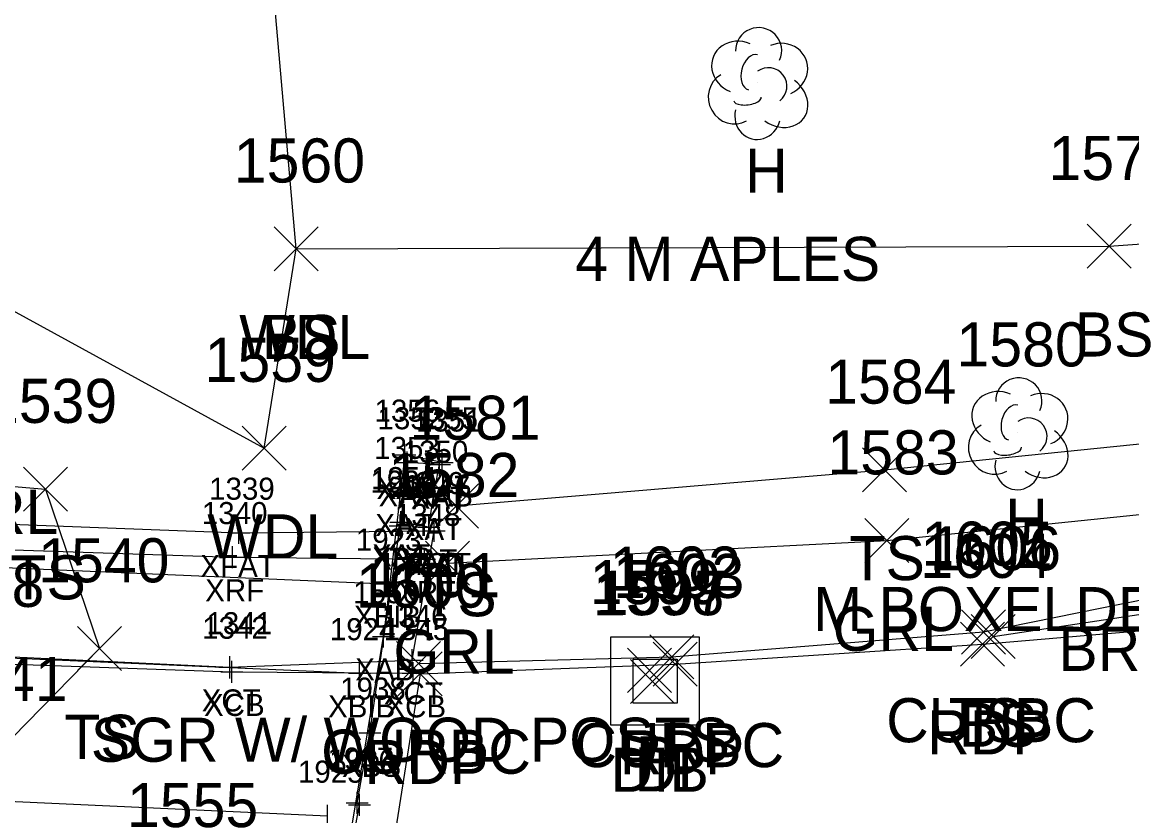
# Model space of a CAD drawing. Extents: x 1761340 to 1763889, y 696770 to 706023.
# Drawn here: x 1761711.3 to 1761761.6, y 700846.3 to 700882.3 of the extents above; entities that cross this region are included whole.
import ezdxf

# ---------------------------------------------------------------- set-up
doc = ezdxf.new("R2010")
doc.units = 0
for name, color, linetype in [('B_A', 7, 'Continuous'), ('B_I', 7, 'Continuous'), ('B_TIC', 7, 'Continuous'), ('BB', 7, 'Continuous'), ('BDC', 7, 'Continuous'), ('BF', 7, 'Continuous'), ('BR', 7, 'Continuous'), ('BSE', 7, 'Continuous'), ('BSUBM', 7, 'Continuous'), ('C_A', 7, 'Continuous'), ('D_A', 7, 'Continuous'), ('D_I', 7, 'Continuous'), ('D_TIC', 7, 'Continuous'), ('DS', 7, 'Continuous'), ('L_A', 7, 'Continuous'), ('L_C', 7, 'Continuous'), ('L_I', 7, 'Continuous'), ('L_TIC', 7, 'Continuous'), ('LAWA', 7, 'Continuous'), ('LELB', 7, 'Continuous'), ('LTD', 7, 'Continuous'), ('P_A', 7, 'Continuous'), ('P_I', 7, 'Continuous'), ('P_TIC', 7, 'Continuous'), ('PET', 7, 'Continuous'), ('R_A', 7, 'Continuous'), ('R_C', 7, 'Continuous'), ('R_I', 7, 'Continuous'), ('R_TIC', 7, 'Continuous'), ('RC', 7, 'Continuous'), ('RGR', 7, 'Continuous'), ('S_C', 7, 'Continuous')]:
    doc.layers.add(name, color=color, linetype=linetype)

msp = doc.modelspace()

# ---------------------------------------------------------------- linework, layer by layer
at = {"layer": 'B_TIC'}
for p, q in [((1761728.645, 700862.669), (1761728.721, 700862.669)), ((1761728.75, 700862.324), (1761728.825, 700862.324)), ((1761730.213, 700862.22), (1761730.289, 700862.22)), ((1761730.336, 700862.319), (1761730.412, 700862.319)), ((1761728.602, 700860.981), (1761728.678, 700860.981)), ((1761729.939, 700860.804), (1761730.014, 700860.804)), ((1761728.433, 700859.454), (1761728.508, 700859.454)), ((1761728.46, 700859.609), (1761728.536, 700859.609)), ((1761728.46, 700859.609), (1761728.536, 700859.609)), ((1761729.726, 700859.385), (1761729.802, 700859.385)), ((1761729.726, 700859.385), (1761729.802, 700859.385)), ((1761729.971, 700859.215), (1761730.046, 700859.215)), ((1761729.971, 700859.215), (1761730.046, 700859.215)), ((1761721.123, 700859.13), (1761721.199, 700859.13)), ((1761720.834, 700858.025), (1761720.91, 700858.025)), ((1761729.543, 700857.943), (1761729.618, 700857.943)), ((1761727.771, 700856.824), (1761727.846, 700856.824)), ((1761727.678, 700854.438), (1761727.753, 700854.438)), ((1761727.678, 700854.438), (1761727.753, 700854.438)), ((1761728.976, 700853.355), (1761729.052, 700853.355)), ((1761720.715, 700853.034), (1761720.79, 700853.034)), ((1761720.805, 700852.829), (1761720.881, 700852.829)), ((1761726.594, 700852.762), (1761726.67, 700852.762)), ((1761729.03, 700852.764), (1761729.105, 700852.764)), ((1761727.06, 700850.068), (1761727.135, 700850.068)), ((1761726.487, 700846.895), (1761726.563, 700846.895)), ((1761726.589, 700846.803), (1761726.665, 700846.803))]:
    msp.add_line(p, q, dxfattribs=at)
for points in [[(1761728.642, 700862.169), (1761728.642, 700863.169)], [(1761728.746, 700861.824), (1761728.746, 700862.824)], [(1761730.21, 700861.72), (1761730.21, 700862.72)], [(1761730.333, 700861.819), (1761730.333, 700862.819)], [(1761728.142, 700862.669), (1761729.142, 700862.669)], [(1761728.246, 700862.324), (1761729.246, 700862.324)], [(1761729.71, 700862.22), (1761730.71, 700862.22)], [(1761729.833, 700862.319), (1761730.833, 700862.319)], [(1761728.599, 700860.481), (1761728.599, 700861.481)], [(1761729.935, 700860.304), (1761729.935, 700861.304)], [(1761728.099, 700860.981), (1761729.099, 700860.981)], [(1761729.435, 700860.804), (1761730.435, 700860.804)], [(1761728.429, 700858.954), (1761728.429, 700859.954)], [(1761728.457, 700859.109), (1761728.457, 700860.109)], [(1761728.457, 700859.109), (1761728.457, 700860.109)], [(1761729.723, 700858.885), (1761729.723, 700859.885)], [(1761729.723, 700858.885), (1761729.723, 700859.885)], [(1761729.967, 700858.715), (1761729.967, 700859.715)], [(1761729.967, 700858.715), (1761729.967, 700859.715)], [(1761721.12, 700858.63), (1761721.12, 700859.63)], [(1761727.929, 700859.454), (1761728.929, 700859.454)], [(1761727.957, 700859.609), (1761728.957, 700859.609)], [(1761727.957, 700859.609), (1761728.957, 700859.609)], [(1761729.223, 700859.385), (1761730.223, 700859.385)], [(1761729.223, 700859.385), (1761730.223, 700859.385)], [(1761729.467, 700859.215), (1761730.467, 700859.215)], [(1761729.467, 700859.215), (1761730.467, 700859.215)], [(1761720.62, 700859.13), (1761721.62, 700859.13)], [(1761720.831, 700857.525), (1761720.831, 700858.525)], [(1761729.539, 700857.443), (1761729.539, 700858.443)], [(1761720.331, 700858.025), (1761721.331, 700858.025)], [(1761729.039, 700857.943), (1761730.039, 700857.943)], [(1761727.767, 700856.324), (1761727.767, 700857.324)], [(1761727.267, 700856.824), (1761728.267, 700856.824)], [(1761727.674, 700853.938), (1761727.674, 700854.938)], [(1761727.674, 700853.938), (1761727.674, 700854.938)], [(1761727.174, 700854.438), (1761728.174, 700854.438)], [(1761727.174, 700854.438), (1761728.174, 700854.438)], [(1761728.973, 700852.855), (1761728.973, 700853.855)], [(1761720.711, 700852.534), (1761720.711, 700853.534)], [(1761720.802, 700852.329), (1761720.802, 700853.329)], [(1761726.591, 700852.262), (1761726.591, 700853.262)], [(1761728.473, 700853.355), (1761729.473, 700853.355)], [(1761729.026, 700852.264), (1761729.026, 700853.264)], [(1761720.211, 700853.034), (1761721.211, 700853.034)], [(1761720.302, 700852.829), (1761721.302, 700852.829)], [(1761726.091, 700852.762), (1761727.091, 700852.762)], [(1761728.526, 700852.764), (1761729.526, 700852.764)], [(1761727.056, 700849.568), (1761727.056, 700850.568)], [(1761726.556, 700850.068), (1761727.556, 700850.068)], [(1761726.484, 700846.395), (1761726.484, 700847.395)], [(1761726.586, 700846.303), (1761726.586, 700847.303)], [(1761725.143, 700845.803), (1761725.143, 700846.803)], [(1761725.984, 700846.895), (1761726.984, 700846.895)], [(1761726.086, 700846.803), (1761727.086, 700846.803)]]:
    msp.add_lwpolyline(points, dxfattribs=at)
at = {"layer": 'BB'}
for points in [[(1761688.646, 700858.499), (1761727.767, 700856.824)], [(1761687.919, 700854.467), (1761726.591, 700852.762)], [(1761686.963, 700848.05), (1761725.143, 700846.303)]]:
    msp.add_lwpolyline(points, dxfattribs=at)
at = {"layer": 'BDC'}
for points in [[(1761603.372, 700879.329), (1761602.459, 700873.228), (1761625.807, 700865.915), (1761643.998, 700861.743), (1761666.42, 700857.506), (1761686.349, 700855.322), (1761703.242, 700853.873), (1761720.711, 700853.034), (1761728.973, 700853.355), (1761729.967, 700859.215)], [(1761602.35, 700873.051), (1761625.784, 700865.689), (1761644.021, 700861.397), (1761666.64, 700857.269), (1761686.143, 700854.84), (1761703.209, 700853.454), (1761720.802, 700852.829), (1761729.026, 700852.764)]]:
    msp.add_lwpolyline(points, dxfattribs=at)
at = {"layer": 'BF'}
msp.add_lwpolyline([(1761603.372, 700879.329), (1761627.262, 700871.889), (1761644.624, 700867.82), (1761667.288, 700863.505), (1761686.862, 700861.108), (1761704.425, 700859.764), (1761721.12, 700859.13), (1761729.967, 700859.215)], dxfattribs=at)
at = {"layer": 'BR'}
msp.add_lwpolyline([(1761603.404, 700877.977), (1761626.827, 700870.765), (1761644.368, 700866.459), (1761666.987, 700862.382), (1761686.603, 700859.803), (1761703.665, 700858.606), (1761720.831, 700858.025), (1761729.539, 700857.943)], dxfattribs=at)
at = {"layer": 'BSE'}
msp.add_lwpolyline([(1761723.35, 700827.699), (1761724.274, 700832.64), (1761724.336, 700832.656), (1761725.187, 700838.449), (1761725.221, 700838.487), (1761725.923, 700842.984), (1761725.977, 700843.546), (1761726.586, 700846.803), (1761726.484, 700846.895), (1761727.056, 700850.068), (1761728.429, 700859.454)], dxfattribs=at)
at = {"layer": 'BSUBM'}
for points in [[(1761730.333, 700862.319), (1761728.642, 700862.669), (1761727.674, 700854.438)], [(1761729.723, 700859.385), (1761729.935, 700860.804), (1761730.21, 700862.22), (1761728.746, 700862.324), (1761728.599, 700860.981), (1761728.457, 700859.609)], [(1761729.723, 700859.385), (1761728.457, 700859.609)], [(1761724.634, 700825.932), (1761724.461, 700823.944), (1761722.479, 700824.16), (1761722.925, 700826.757), (1761723.41, 700828.779), (1761727.674, 700854.438)]]:
    msp.add_lwpolyline(points, dxfattribs=at)
at = {"layer": 'D_TIC'}
for points in [[(1761738.729, 700851.898), (1761740.729, 700853.898)], [(1761740.729, 700851.898), (1761738.729, 700853.898)], [(1761738.865, 700851.393), (1761740.865, 700853.393)], [(1761740.865, 700851.393), (1761738.865, 700853.393)]]:
    msp.add_lwpolyline(points, dxfattribs=at)
at = {"layer": 'DS'}
for p, q in [((1761737.987, 700854.41), (1761741.987, 700854.41)), ((1761737.987, 700850.41), (1761737.987, 700854.41)), ((1761741.987, 700854.41), (1761741.987, 700850.41)), ((1761738.987, 700851.41), (1761738.987, 700853.41)), ((1761738.987, 700853.41), (1761740.987, 700853.41)), ((1761740.987, 700853.41), (1761740.987, 700851.41)), ((1761739.992, 700852.412), (1761739.992, 700852.412)), ((1761739.992, 700852.412), (1761739.992, 700852.412)), ((1761740.987, 700851.41), (1761738.987, 700851.41)), ((1761741.987, 700850.41), (1761737.987, 700850.41))]:
    msp.add_line(p, q, dxfattribs=at)
at = {"layer": 'L_TIC'}
for points in [[(1761722.716, 700871.008), (1761724.716, 700873.008)], [(1761724.716, 700871.008), (1761722.716, 700873.008)], [(1761722.716, 700871.008), (1761724.716, 700873.008)], [(1761724.716, 700871.008), (1761722.716, 700873.008)], [(1761759.57, 700871.122), (1761761.57, 700873.122)], [(1761761.57, 700871.122), (1761759.57, 700873.122)], [(1761721.268, 700861.97), (1761723.268, 700863.97)], [(1761723.268, 700861.97), (1761721.268, 700863.97)], [(1761749.391, 700860.984), (1761751.391, 700862.984)], [(1761751.391, 700860.984), (1761749.391, 700862.984)], [(1761711.355, 700860.111), (1761713.355, 700862.111)], [(1761713.355, 700860.111), (1761711.355, 700862.111)], [(1761729.978, 700859.347), (1761731.978, 700861.347)], [(1761731.978, 700859.347), (1761729.978, 700861.347)], [(1761753.879, 700853.636), (1761755.879, 700855.636)], [(1761755.879, 700853.636), (1761753.879, 700855.636)], [(1761754.317, 700853.431), (1761756.317, 700855.431)], [(1761756.317, 700853.431), (1761754.317, 700855.431)], [(1761713.798, 700852.885), (1761715.798, 700854.885)], [(1761715.798, 700852.885), (1761713.798, 700854.885)]]:
    msp.add_lwpolyline(points, dxfattribs=at)
at = {"layer": 'LAWA'}
msp.add_lwpolyline([(1761696.403, 700877.132), (1761722.268, 700862.97), (1761723.716, 700872.008), (1761721.644, 700895.629), (1761726.277, 700910.333), (1761732.763, 700919.168), (1761734.997, 700942.591)], dxfattribs=at)
at = {"layer": 'LELB'}
for points in [[(1761723.716, 700872.008), (1761760.57, 700872.122), (1761783.532, 700873.77), (1761799.17, 700869.892), (1761806.338, 700870.908), (1761834.789, 700874.305), (1761863.419, 700878.597), (1761884.027, 700880.868), (1761911.516, 700884.533), (1761932.354, 700886.896), (1761937.155, 700891.638), (1761941.248, 700901.223)], [(1761730.978, 700860.347), (1761750.391, 700861.984), (1761774.561, 700864.449), (1761784.543, 700864.299)], [(1761754.879, 700854.636), (1761779.614, 700859.653), (1761806.29, 700864.673)], [(1761755.317, 700854.431), (1761780.015, 700858.17), (1761806.29, 700864.673)], [(1761687.875, 700863.195), (1761712.355, 700861.111), (1761714.798, 700853.885), (1761709.534, 700848.506), (1761700.41, 700847.52), (1761692.689, 700848.437), (1761689.436, 700852.719)]]:
    msp.add_lwpolyline(points, dxfattribs=at)
at = {"layer": 'LTD'}
for p, q in [((1761744.635, 700879.551), (1761744.635, 700879.551)), ((1761744.635, 700879.551), (1761744.635, 700879.551)), ((1761756.429, 700863.673), (1761756.429, 700863.673)), ((1761756.429, 700863.673), (1761756.429, 700863.673))]:
    msp.add_line(p, q, dxfattribs=at)
for centre in [(1761744.681, 700880.985), (1761756.476, 700865.107)]:
    msp.add_arc(centre, 1.047, 335.5272, 180.9563, dxfattribs=at)
for centre, major_axis, ratio, start_param, end_param in [((1761743.843, 700880.217), (1.21, -0.512), 0.895232, 1.570796, 4.712389), ((1761745.676, 700880.134), (-1.141, -0.483), 0.949671, 1.570796, 4.712389), ((1761744.426, 700880.009), (-0.208, -0.792), 0.645439, 3.141593, 6.283185), ((1761745.135, 700879.384), (-0.5, 0.667), 0.989748, 3.141593, 6.283185), ((1761743.551, 700878.842), (0.584, -1.042), 0.959034, 3.141593, 6.283185), ((1761745.635, 700878.717), (-1.09, 0.792), 0.841452, 1.570796, 4.712389), ((1761744.176, 700878.8), (-0.625, -0.083), 0.423636, 0, 3.141593), ((1761744.635, 700878.051), (0.265, 1.061), 0.942809, 1.570796, 4.712389), ((1761755.638, 700864.339), (1.21, -0.512), 0.895232, 1.570796, 4.712389), ((1761757.471, 700864.256), (-1.141, -0.483), 0.949671, 1.570796, 4.712389), ((1761756.221, 700864.131), (-0.208, -0.792), 0.645439, 3.141593, 6.283185), ((1761756.929, 700863.506), (-0.5, 0.667), 0.989748, 3.141593, 6.283185), ((1761755.346, 700862.964), (0.584, -1.042), 0.959034, 3.141593, 6.283185), ((1761757.429, 700862.839), (-1.09, 0.792), 0.841452, 1.570796, 4.712389), ((1761755.971, 700862.923), (-0.625, -0.083), 0.423636, 0, 3.141593), ((1761756.43, 700862.173), (0.265, 1.061), 0.942809, 1.570796, 4.712389)]:
    msp.add_ellipse(centre, major_axis=major_axis, ratio=ratio, start_param=start_param, end_param=end_param, dxfattribs=at)
at = {"layer": 'P_TIC'}
for points in [[(1761753.829, 700853.087), (1761755.829, 700855.087)], [(1761755.829, 700853.087), (1761753.829, 700855.087)], [(1761739.899, 700852.176), (1761741.899, 700854.176)], [(1761741.899, 700852.176), (1761739.899, 700854.176)], [(1761728.332, 700851.74), (1761730.332, 700853.74)], [(1761730.332, 700851.74), (1761728.332, 700853.74)], [(1761728.332, 700851.74), (1761730.332, 700853.74)], [(1761730.332, 700851.74), (1761728.332, 700853.74)]]:
    msp.add_lwpolyline(points, dxfattribs=at)
at = {"layer": 'PET'}
for points in [[(1761729.332, 700852.74), (1761740.899, 700853.176), (1761754.829, 700854.087), (1761780.546, 700856.275), (1761810.222, 700861.143), (1761821.192, 700866.007), (1761839.219, 700868.834), (1761861.11, 700872.048), (1761884.874, 700875.705), (1761913.75, 700879.268), (1761932.441, 700880.62), (1761962.057, 700884.589), (1761979.873, 700885.617), (1762011.623, 700885.448), (1762036.796, 700884.842)], [(1761729.332, 700852.74), (1761727.434, 700840.665), (1761725.471, 700828.383), (1761741.06, 700828.317), (1761766.654, 700830.86), (1761785.895, 700834.25), (1761810.857, 700839.794), (1761840.513, 700846.054), (1761863.887, 700848.795), (1761886.859, 700850.872), (1761909.086, 700853.948), (1761931.553, 700856.455), (1761961.834, 700859.608), (1761986.639, 700861.179), (1762018.608, 700861.2), (1762035.735, 700860.872)]]:
    msp.add_lwpolyline(points, dxfattribs=at)
at = {"layer": 'R_TIC'}
for points in [[(1761749.494, 700857.778), (1761751.494, 700859.778)], [(1761751.494, 700857.778), (1761749.494, 700859.778)], [(1761729.58, 700856.751), (1761731.58, 700858.751)], [(1761731.58, 700856.751), (1761729.58, 700858.751)], [(1761753.879, 700853.636), (1761755.879, 700855.636)], [(1761755.879, 700853.636), (1761753.879, 700855.636)], [(1761728.262, 700852.21), (1761730.262, 700854.21)], [(1761730.262, 700852.21), (1761728.262, 700854.21)], [(1761739.746, 700852.507), (1761741.746, 700854.507)], [(1761741.746, 700852.507), (1761739.746, 700854.507)]]:
    msp.add_lwpolyline(points, dxfattribs=at)
at = {"layer": 'RC'}
msp.add_lwpolyline([(1761729.262, 700853.21), (1761740.746, 700853.507), (1761754.879, 700854.636)], dxfattribs=at)
at = {"layer": 'RGR'}
msp.add_lwpolyline([(1761730.58, 700857.751), (1761750.494, 700858.778), (1761767.085, 700860.494), (1761784.543, 700864.299), (1761805.335, 700869.042)], dxfattribs=at)

# ---------------------------------------------------------------- texts
at = {"layer": 'B_A'}
for s, p in [('XAB', (1761727.362, 700860.669)), ('XAT', (1761727.451, 700860.324)), ('XAT', (1761728.915, 700860.22)), ('XAB', (1761729.053, 700860.319)), ('XAT', (1761727.304, 700858.981)), ('XAT', (1761728.64, 700858.804)), ('XAT', (1761727.162, 700857.609)), ('XAT', (1761727.162, 700857.609)), ('XBS', (1761727.17, 700857.454)), ('XFAT', (1761728.223, 700857.215)), ('XAT', (1761728.427, 700857.385)), ('XAT', (1761728.427, 700857.385)), ('XCT', (1761728.688, 700857.215)), ('XFAT', (1761719.376, 700857.13)), ('XRF', (1761719.591, 700856.025)), ('XRF', (1761728.299, 700855.943)), ('XBIB', (1761726.338, 700854.824)), ('XAB', (1761726.395, 700852.438)), ('XAB', (1761726.395, 700852.438)), ('XCT', (1761727.693, 700851.355)), ('XCT', (1761719.432, 700851.034)), ('XCB', (1761719.538, 700850.829)), ('XBIB', (1761725.162, 700850.762)), ('XCB', (1761727.763, 700850.764)), ('XBS', (1761725.796, 700848.068))]:
    msp.add_text(s, height=1, dxfattribs=at).set_placement(p)
at = {"layer": 'B_I'}
for s, p in [('1356', (1761727.268, 700864.169)), ('1352', (1761727.4, 700863.824)), ('1355', (1761728.987, 700863.819)), ('1351', (1761729.147, 700863.72)), ('1353', (1761727.252, 700862.481)), ('1350', (1761728.545, 700862.304)), ('1939', (1761727.079, 700860.954)), ('1354', (1761727.11, 700861.109)), ('1354', (1761727.11, 700861.109)), ('1349', (1761728.372, 700860.885)), ('1349', (1761728.372, 700860.885)), ('1347', (1761728.621, 700860.715)), ('1347', (1761728.621, 700860.715)), ('1339', (1761719.77, 700860.63)), ('1340', (1761719.441, 700859.525)), ('1348', (1761728.193, 700859.443)), ('1923', (1761726.421, 700858.324)), ('1556', (1761726.3, 700855.938)), ('1556', (1761726.3, 700855.938)), ('1346', (1761727.599, 700854.855)), ('1342', (1761719.455, 700854.329)), ('1341', (1761719.648, 700854.534)), ('1924', (1761725.244, 700854.262)), ('1345', (1761727.68, 700854.264)), ('1938', (1761725.71, 700851.568)), ('1937', (1761725.137, 700848.395)), ('1936', (1761725.212, 700848.303)), ('1925', (1761723.797, 700847.803))]:
    msp.add_text(s, height=1, dxfattribs=at).set_placement(p)
at = {"layer": 'C_A'}
msp.add_text('HVCTRL', height=2, dxfattribs=at).set_placement((1761702.238, 700859.084))
at = {"layer": 'D_A'}
for s, p in [('P', (1761739.107, 700847.898)), ('DIB', (1761737.967, 700847.393)), ('DI', (1761739.047, 700847.412))]:
    msp.add_text(s, height=2, dxfattribs=at).set_placement(p)
at = {"layer": 'D_I'}
for s, p in [('1599', (1761737.028, 700855.898)), ('1598', (1761737.172, 700855.393)), ('1597', (1761737.299, 700855.412))]:
    msp.add_text(s, height=2, dxfattribs=at).set_placement(p)
at = {"layer": 'L_A'}
for s, p in [('H', (1761744.068, 700874.551)), ('WDL', (1761721.133, 700867.008)), ('BS', (1761722.156, 700867.008)), ('BS', (1761759.011, 700867.122)), ('H', (1761755.862, 700858.673)), ('WDL', (1761719.686, 700857.97)), ('TS', (1761748.8, 700856.984)), ('TS', (1761710.764, 700856.111)), ('TS', (1761729.388, 700855.347)), ('TS', (1761753.289, 700849.636)), ('BS', (1761753.758, 700849.431)), ('TS', (1761713.207, 700848.885))]:
    msp.add_text(s, height=2, dxfattribs=at).set_placement(p)
at = {"layer": 'L_C'}
for s, p in [('4 M APLES', (1761736.367, 700870.551)), ('M BOXELDER', (1761747.146, 700854.673))]:
    msp.add_text(s, height=2, dxfattribs=at).set_placement(p)
at = {"layer": 'L_I'}
for s, p in [('1560', (1761720.889, 700875.008)), ('1560', (1761720.889, 700875.008)), ('1576', (1761757.822, 700875.122)), ('1580', (1761753.65, 700866.673)), ('1559', (1761719.568, 700865.97)), ('1584', (1761747.698, 700864.984)), ('1539', (1761709.654, 700864.111)), ('1581', (1761728.852, 700863.347)), ('1605', (1761752.061, 700857.636)), ('1606', (1761752.443, 700857.431)), ('1540', (1761712.019, 700856.885)), ('1538', (1761706.353, 700855.771)), ('1541', (1761707.408, 700851.506)), ('1555', (1761716.046, 700845.789))]:
    msp.add_text(s, height=2, dxfattribs=at).set_placement(p)
at = {"layer": 'P_A'}
for p in [(1761752.317, 700849.087), (1761738.388, 700848.176), (1761726.821, 700847.74), (1761726.821, 700847.74)]:
    msp.add_text('RDP', height=2, dxfattribs=at).set_placement(p)
at = {"layer": 'P_I'}
for s, p in [('1604', (1761752.01, 700857.087)), ('1603', (1761738.081, 700856.176)), ('1600', (1761726.427, 700855.74)), ('1600', (1761726.427, 700855.74))]:
    msp.add_text(s, height=2, dxfattribs=at).set_placement(p)
at = {"layer": 'R_A'}
for s, p in [('GRL', (1761748.037, 700853.778)), ('GRL', (1761728.124, 700852.751)), ('CURBC', (1761750.462, 700849.636)), ('CURBC', (1761724.845, 700848.21)), ('CURBC', (1761736.329, 700848.507))]:
    msp.add_text(s, height=2, dxfattribs=at).set_placement(p)
at = {"layer": 'R_C'}
msp.add_text('SGR W/ WOOD POSTS', height=2, dxfattribs=at).set_placement((1761714.407, 700848.751))
at = {"layer": 'R_I'}
for s, p in [('1583', (1761747.801, 700861.778)), ('1582', (1761727.888, 700860.751)), ('1605', (1761752.061, 700857.636)), ('1601', (1761727.01, 700856.21)), ('1602', (1761737.928, 700856.507))]:
    msp.add_text(s, height=2, dxfattribs=at).set_placement(p)
at = {"layer": 'S_C'}
msp.add_text('BRIDGE 6 VT 2B', height=2, dxfattribs=at).set_placement((1761758.267, 700852.871))

doc.saveas('drawing.dxf')
